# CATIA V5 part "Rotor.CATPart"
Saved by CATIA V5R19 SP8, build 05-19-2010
Part number: Rotor
Nomenclature: 69_a
Bounding box of the stored display mesh (mm): x -234 to 0, y -41.988 to 41.988, z -42 to 42
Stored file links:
  C:\Users\rphgr\Desktop\0_Tapis_TC520B_vitesse\Rotor.CATPart
  D:\Documents\1_Travail\1 - ac-limoges.fr\ac-limoges.fr\Emmanuel Maynard - STI2D_Turgot\3 - Supports\Tapis de course TC520B\Tapis de course TC520B_Ca\0_Tapis_TC520B.CATProduct
  D:\Documents\1_Travail\1 - ac-limoges.fr\ac-limoges.fr\Emmanuel Maynard - STI2D_Turgot\3 - Supports\Tapis de course TC520B\Tapis de course TC520B_Ca\Moteur_Tapis_Stator.CATPart
  D:\Programmes\DassaultSysteme\win_b64\reffiles\standard\MetricThickPitch.txt
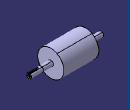
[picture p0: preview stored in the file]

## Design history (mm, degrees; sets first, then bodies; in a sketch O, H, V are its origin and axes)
AxisSystem1: origin (0, 0, 0), X (1, 0, 0), Y (0, 1, 0), Z (0, 0, 1)
Set1
  DatumSurface1
Body1 (main body)
  Sketch1 on ZX plane of AxisSystem1, origin (0, 0, 0), H (0, 0, 1), V (1, 0, 0)
    point P1 (0, 0)
    line L1 (0, 0) -> (8, 0)
    line L2 (8, 0) -> (8, -39)
    line L3 (8.5, -71) -> (42, -71)
    line L4 (42, -71) -> (42, -184)
    line L5 (42, -184) -> (8, -184)
    point P5 (8, -184)
    line L6 (8, -184) -> (8, -234)
    line L7 (8, -234) -> (0, -234)
    point P7 (0, -234)
    axis line L8 (0, 0) -> (0, -370.0566)
    reference intersected line E1 through (0, 0) direction (-1, 0) from YZ plane of AxisSystem1
    line L9 (8, -39) -> (8.5, -39)
    line L10 (8.5, -39) -> (8.5, -71)
    reference intersected line E2 through (0, 0) direction (-1, 0) from YZ plane of AxisSystem1
    reference intersected line E3 through (0, 0) direction (-1, 0) from YZ plane of AxisSystem1
    reference intersected line E4 through (0, -239) direction (1, 0) from face of DatumSurface1
    distance L5 L7 = 50
    distance E2 L3 = 71
    distance L9 E3 = 39
    distance L2 L8 = 8
    distance L10 L8 = 8.5
    distance L4 L8 = 42
    distance L7 E4 = 5
    coincidence: P1 V, P5 L2, P7 V, L1 E1
    horizontal: L1 H, L3 H, L5 H, L7 H, L9 H
    vertical: L2 V, L4 V, L6 V, L8 V, L10 V
  Shaft1: profile Sketch1, axis Sketch1.L8, angle 360
  Plane1: type Tangent, Support face of Shaft1 from Sketch1.L2, RefPoint {point type OnCurve, Support edge [face of Shaft1 from Sketch1.L1 | face of Shaft1 from Sketch1.L2], RefPoint {extremum Reference edge [face of Shaft1 from Sketch1.L1 | face of Shaft1 from Sketch1.L2], Direction (1, 2, 3)}, Length 45.073}
  Sketch2 on Plane1, origin (0, -0.4882, 7.9851), H (-1, 0, 0), V (0, 0.9981, 0.061)
    construction line L1 (28, 0) -> (0, 0)
    point P1 (28, 0)
    point P2 (0, 0)
    line L2 (28, -2.5) -> (0, -2.5)
    line L3 (0, 2.5) -> (28, 2.5)
    arc A1 centre (0, 0) radius 2.5 from (0, -2.5) to (0, 2.5) cw
    arc A2 centre (28, 0) radius 2.5 from (28, 2.5) to (28, -2.5) cw
    reference projected line E1 through (0, 0) direction (1, 0) from axis of face of Shaft1 from Sketch1.L2
    reference intersected point E2 (0, 0) from face of Shaft1 from Sketch1.L1
    reference intersected point E3 (0, 0) from face of Shaft1 from Sketch1.L1
    distance L1 L2 = 2.5
    distance P1 E2 = 28
    horizontal: L1 H
    tangency: A1 L2, A2 L2, A1 L3, A2 L3
    coincidence: L1 E1, P2 E3
  Pocket1: profile Sketch2, direction (0, 0.061, -0.9981), length 3.2
  Sketch3 on face of Shaft1 from Sketch1.L1, origin (0, 0, 0), H (0, 1, 0), V (0, 0, 1)
    point P1 (0, 0)
    reference projected point E1 (0, 0) from vertex [YZ plane of AxisSystem1 | ZX plane of AxisSystem1 | XY plane of AxisSystem1]
    coincidence: E1 P1
  Hole1: placed by Sketch3, at (0, 0, 0) direction (-1, 0, 0), diameter 4.917, depth 22, V-bottom angle 120, countersink depth 1, countersink angle 90, threaded "M6", thread diameter 6, thread depth 15, pitch 1
  Chamfer1: length 1, angle 45, on edge [face of Shaft1 from Sketch1.L1 | face of Shaft1 from Sketch1.L2]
